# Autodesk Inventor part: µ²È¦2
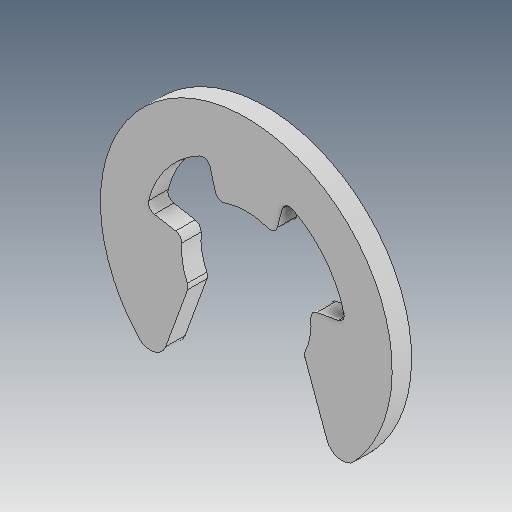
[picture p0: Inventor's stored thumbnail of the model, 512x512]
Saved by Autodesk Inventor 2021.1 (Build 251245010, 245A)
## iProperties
Created: 2013-04
Part Number: µ²È¦2
Material: Ogólny
Document SubType Name: Modeling
Designer: user
Density: 1 g/cm^3
Appearance: Domyślna
Author: user
Revision Number: ÈÎºÎ
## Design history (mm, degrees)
feature "À­Éì1"
node "Bryła1"
